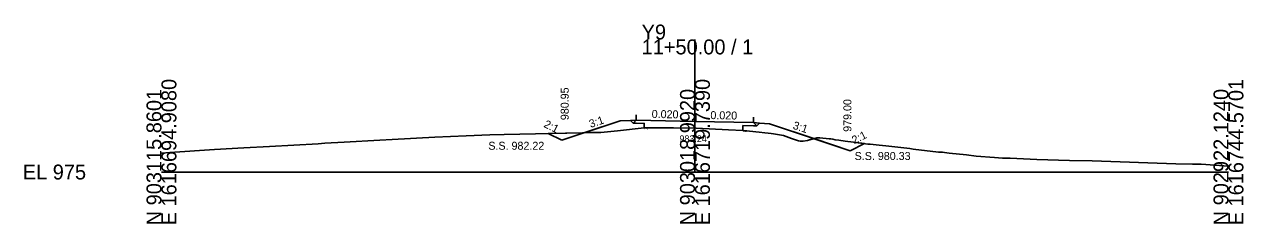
# Model space of a CAD drawing. Extents: x -26 to 1403, y -10 to 3021.
# Drawn here: x -25.7 to 202.8, y 1490.3 to 1527.7 of the extents above; entities that cross this region are included whole.
import ezdxf

# ---------------------------------------------------------------- set-up
doc = ezdxf.new("R2010")
doc.units = 0
for name, color, linetype in [('Exist Cross Section Cell', 7, 'Continuous'), ('Exist XS Center Line Elevation Label', 7, 'Continuous'), ('Exist XS Ground Line', 7, 'Continuous'), ('Prop XS Dump Level', 7, 'Continuous'), ('Prop XS Earthwork Shape', 7, 'Continuous'), ('Prop XS EOT Tick Mark', 7, 'Continuous'), ('Prop XS Finish Grade', 7, 'Continuous'), ('Prop XS Finish Grade Earthwork', 7, 'Continuous'), ('Prop XS Finish Grade Pavement', 7, 'Continuous'), ('Prop XS Pvmt Edge Slope', 7, 'Continuous'), ('Prop XS SE Text', 7, 'Continuous'), ('Prop XS SS Elevation Text', 7, 'Continuous'), ('Prop XS Subgrade Earthwork', 7, 'Continuous')]:
    doc.layers.add(name, color=color, linetype=linetype)

msp = doc.modelspace()

# ---------------------------------------------------------------- linework, layer by layer
at = {"layer": 'Exist Cross Section Cell'}
for p, q in [((100, 1500), (100, 1524.88)), ((0, 1500), (100, 1500)), ((100, 1500), (200, 1500))]:
    msp.add_line(p, q, dxfattribs=at)
at = {"layer": 'Exist XS Ground Line'}
for p, q in [((40.93, 1505.98), (43.23, 1506.11)), ((43.23, 1506.11), (51.25, 1506.57)), ((51.25, 1506.57), (57.11, 1506.82)), ((57.11, 1506.82), (61.58, 1506.98)), ((61.58, 1506.98), (64.22, 1507.02)), ((64.22, 1507.02), (78.92, 1507.38)), ((78.92, 1507.38), (81.6, 1507.42)), ((81.6, 1507.42), (82.35, 1507.42)), ((82.35, 1507.42), (85.48, 1507.74)), ((85.48, 1507.74), (90.5, 1508.29)), ((90.5, 1508.29), (95.95, 1508.28)), ((95.95, 1508.28), (100.25, 1508.24)), ((100.25, 1508.24), (106.27, 1507.95)), ((106.27, 1507.95), (108.95, 1507.82)), ((108.95, 1507.82), (109.34, 1507.76)), ((109.34, 1507.76), (109.72, 1507.73)), ((109.72, 1507.73), (110.25, 1507.69)), ((110.25, 1507.69), (112.06, 1507.47)), ((112.06, 1507.47), (113.09, 1507.34)), ((113.09, 1507.34), (113.74, 1507.27)), ((113.74, 1507.27), (114.3, 1507.2)), ((114.3, 1507.2), (114.74, 1507.15)), ((114.74, 1507.15), (116.58, 1506.84)), ((116.58, 1506.84), (118.08, 1506.27)), ((118.08, 1506.27), (119.42, 1505.84)), ((121.08, 1505.9), (122.84, 1506.43)), ((122.84, 1506.43), (123.39, 1506.4)), ((123.39, 1506.4), (125.18, 1506.26)), ((125.18, 1506.26), (125.49, 1506.21)), ((125.49, 1506.21), (125.86, 1506.15)), ((125.86, 1506.15), (126.31, 1506.07)), ((126.31, 1506.07), (126.97, 1505.99)), ((1.58, 1503.66), (9.96, 1504.25)), ((9.96, 1504.25), (15.47, 1504.53)), ((15.47, 1504.53), (20.28, 1504.8)), ((20.28, 1504.8), (29.35, 1505.32)), ((29.35, 1505.32), (30.61, 1505.4)), ((30.61, 1505.4), (34.25, 1505.61)), ((34.25, 1505.61), (40.93, 1505.98)), ((119.42, 1505.84), (119.73, 1505.78)), ((119.73, 1505.78), (120.26, 1505.8)), ((120.26, 1505.8), (121.08, 1505.9)), ((126.97, 1505.99), (128.13, 1505.8)), ((128.13, 1505.8), (129.73, 1505.6)), ((129.73, 1505.6), (132.41, 1505.25)), ((132.41, 1505.25), (132.81, 1505.2)), ((132.81, 1505.2), (134.51, 1505.03)), ((134.51, 1505.03), (135.77, 1504.91)), ((135.77, 1504.91), (140.27, 1504.39)), ((140.27, 1504.39), (140.93, 1504.31)), ((140.93, 1504.31), (145.65, 1503.75)), ((145.65, 1503.75), (146.42, 1503.7)), ((0, 1503.56), (1.58, 1503.66)), ((146.42, 1503.7), (146.8, 1503.64)), ((146.8, 1503.64), (147.66, 1503.54)), ((147.66, 1503.54), (150.89, 1503.2)), ((150.89, 1503.2), (152.68, 1502.96)), ((152.68, 1502.96), (156.17, 1502.73)), ((156.17, 1502.73), (157.62, 1502.63)), ((157.62, 1502.63), (159.11, 1502.57)), ((159.11, 1502.57), (164.08, 1502.38)), ((164.08, 1502.38), (170.21, 1502.19)), ((170.21, 1502.19), (174.44, 1502.11)), ((174.44, 1502.11), (190.16, 1501.53)), ((190.16, 1501.53), (193.25, 1501.49)), ((193.25, 1501.49), (194.88, 1501.47)), ((194.88, 1501.47), (200, 1501.1))]:
    msp.add_line(p, q, dxfattribs=at)
at = {"layer": 'Prop XS Dump Level'}
for p, q in [((89, 1509.72), (100, 1509.5)), ((100, 1509.5), (111, 1509.28))]:
    msp.add_line(p, q, dxfattribs=at)
at = {"layer": 'Prop XS Earthwork Shape'}
for points in [[(86, 1509.6), (79.36, 1507.39), (81.6, 1507.42), (82.35, 1507.42), (85.48, 1507.74), (90.5, 1508.29), (90.5, 1509.11), (89, 1509.14), (88.43, 1509.15), (87.9, 1509.68)], [(108.95, 1508.74), (111, 1508.7), (111.6, 1508.68), (112.1, 1509.19), (114, 1509.04), (122.31, 1506.27), (121.08, 1505.9), (120.26, 1505.8), (119.73, 1505.78), (119.42, 1505.84), (118.08, 1506.27), (116.58, 1506.84), (114.74, 1507.15), (114.3, 1507.2), (113.74, 1507.27), (113.09, 1507.34), (112.06, 1507.47), (110.25, 1507.69), (109.72, 1507.73), (109.34, 1507.76), (108.95, 1507.82)], [(75.05, 1505.95), (72.5, 1507.22), (78.92, 1507.38), (79.36, 1507.39)], [(122.31, 1506.27), (122.84, 1506.43), (123.39, 1506.4), (125.18, 1506.26), (125.49, 1506.21), (125.86, 1506.15), (126.31, 1506.07), (126.97, 1505.99), (128.13, 1505.8), (129.73, 1505.6), (131.78, 1505.33), (129.12, 1504)]]:
    msp.add_lwpolyline(points, close=True, dxfattribs=at)
at = {"layer": 'Prop XS EOT Tick Mark'}
for p, q in [((89, 1509.72), (89, 1510.72)), ((111, 1509.28), (111, 1510.28))]:
    msp.add_line(p, q, dxfattribs=at)
at = {"layer": 'Prop XS Finish Grade'}
for p, q in [((89, 1509.72), (87.9, 1509.68)), ((111, 1509.28), (112.1, 1509.19))]:
    msp.add_line(p, q, dxfattribs=at)
at = {"layer": 'Prop XS Finish Grade Earthwork'}
for p, q in [((86, 1509.6), (75.05, 1505.95)), ((87.9, 1509.68), (86, 1509.6)), ((112.1, 1509.19), (114, 1509.04)), ((114, 1509.04), (129.12, 1504)), ((75.05, 1505.95), (72.5, 1507.22)), ((131.78, 1505.33), (129.12, 1504))]:
    msp.add_line(p, q, dxfattribs=at)
at = {"layer": 'Prop XS Finish Grade Pavement'}
for p, q in [((89, 1509.72), (100, 1509.5)), ((100, 1509.5), (111, 1509.28))]:
    msp.add_line(p, q, dxfattribs=at)
at = {"layer": 'Prop XS Pvmt Edge Slope'}
for p, q in [((89, 1509.72), (88.43, 1509.15)), ((111, 1509.28), (111.6, 1508.68))]:
    msp.add_line(p, q, dxfattribs=at)
at = {"layer": 'Prop XS Subgrade Earthwork'}
for p, q in [((88.43, 1509.15), (87.9, 1509.68)), ((89, 1509.14), (88.43, 1509.15)), ((90.5, 1509.11), (89, 1509.14)), ((90.5, 1509.11), (90.5, 1508.29)), ((108.95, 1508.74), (108.95, 1507.82)), ((108.95, 1508.74), (111, 1508.7)), ((111, 1508.7), (111.6, 1508.68)), ((111.6, 1508.68), (112.1, 1509.19))]:
    msp.add_line(p, q, dxfattribs=at)

# ---------------------------------------------------------------- texts
at = {"layer": 'Exist Cross Section Cell'}
for s, p in [('Y9', (90, 1524.88)), ('11+50.00 / 1', (90, 1522.08)), ('EL 975', (-26, 1498.6))]:
    msp.add_text(s, height=2.8, dxfattribs=at).set_placement(p)
for s, p in [('N 903115.8601', (0, 1490)), ('E 1616694.9080', (2.8, 1490)), ('N 903018.9920', (100, 1490)), ('E 1616719.7390', (102.8, 1490)), ('N 902922.1240', (200, 1490)), ('E 1616744.5701', (202.8, 1490))]:
    msp.add_text(s, height=2.8, rotation=90, dxfattribs=at).set_placement(p)
at = {"layer": 'Exist XS Center Line Elevation Label'}
msp.add_text('983.24', height=1.25, dxfattribs=at).set_placement((97.1, 1505.62))
at = {"layer": 'Prop XS Dump Level'}
for s, height, p in [('Case1', 0.04, (86, 1509.56)), ('Case1', 0.04, (114, 1509)), ('Eop', 0.3, (90.5, 1507.99)), ('Eop', 0.3, (108.95, 1507.52))]:
    msp.add_text(s, height=height, dxfattribs=at).set_placement(p)
at = {"layer": 'Prop XS SE Text'}
for p in [(91.88, 1510.16), (102.88, 1509.94)]:
    msp.add_text('0.020', height=1.5, rotation=358.8542, dxfattribs=at).set_placement(p)
at = {"layer": 'Prop XS SS Elevation Text'}
for s, rotation, p in [('980.95', 90, (76.33, 1509.74)), ('979.00', 90, (129.32, 1507.55)), ('2:1', 333.4349, (71.53, 1508.51)), ('3:1', 18.4349, (80.44, 1508.27)), ('3:1', 341.5651, (118.22, 1508.15)), ('2:1', 26.5651, (129.86, 1505.21))]:
    msp.add_text(s, height=1.5, rotation=rotation, dxfattribs=at).set_placement(p)
for s, p in [('S.S. 982.22', (61.27, 1504.18)), ('S.S. 980.33', (129.93, 1502.26))]:
    msp.add_text(s, height=1.5, dxfattribs=at).set_placement(p)

doc.saveas('drawing.dxf')
